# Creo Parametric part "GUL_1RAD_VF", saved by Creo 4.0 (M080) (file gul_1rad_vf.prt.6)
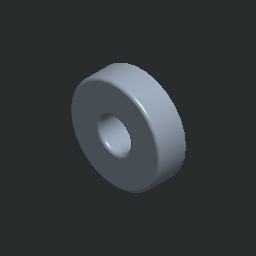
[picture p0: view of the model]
Units: millimeter Kilogram Sec (mmKs); MM, KILOGRAM, SECS
Materials in the file: OCEL_N

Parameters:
  MFG_WP_MATERIAL = "RO5"
  NAZOV = "GUL_1RAD_VF"
  PTC_MATERIAL_NAME = "OCEL_N"

Other parameters: HMOTNOST, HUSTOTA

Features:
  1. round
  2. round

Named dimensions: velke_D

Layers: 1, 2, 3, 4, 5, 6, 7, 8, 9, 10, 11, 12, 13, 14, 15, 16, 17, 18, 19, 20, 21, 22, 23, 24, 25, 26, 27, 28, 29, 30, 31, 32

Family table entries: GENERIC, LOZISKO_B7200CBTB, GUL_1RAD_VF, value(d_val), 2/>, 2/", value(i_val), LOZISKO_B7200CATB, GUL_1RAD_VF, !/$, 2/>, 2/", LOZISKO_B7201CBTB, GUL_1RAD_VF, !/(, 2/@, 2/$, LOZISKO_B7201CATB, GUL_1RAD_VF, !/(, 2/@, 2/$, LOZISKO_A7201AATA, GUL_1RAD_VF, !/(, 2/@, 2/$, LOZISKO_B7202CBTB, GUL_1RAD_VF, !/., 2/&, LOZISKO_B7202CATB, GUL_1RAD_VF, !/., 2/&, LOZISKO_B7203CBTB, GUL_1RAD_VF, !/1, 2/D, 2/(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

Surfaces: 8 torus, 2 plane, 2 cylinder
